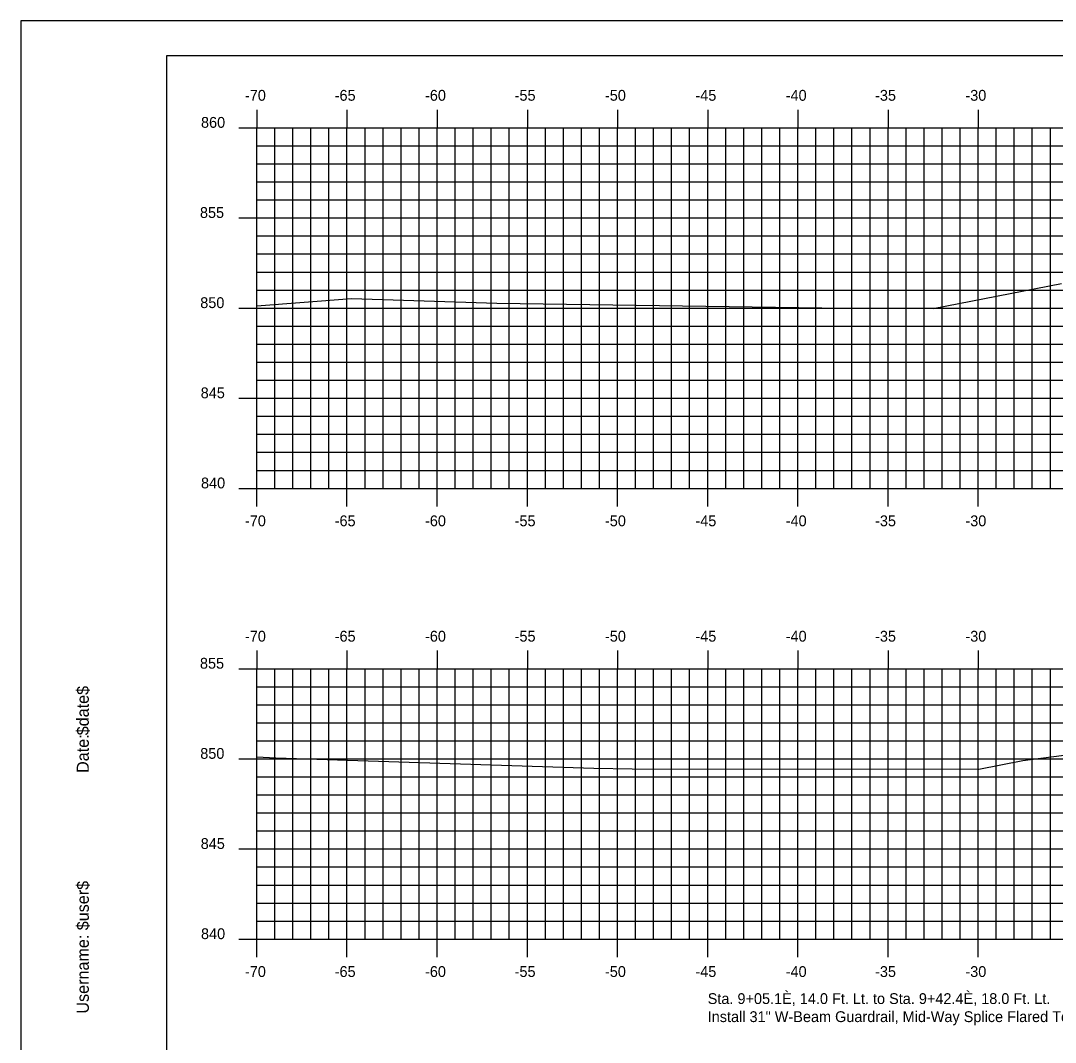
# Model space of a CAD drawing. Extents: x 2194502 to 2194968, y 863888 to 863998.
# Drawn here: x 2194615.4 to 2194672.8, y 863941.7 to 863998.4 of the extents above; entities that cross this region are included whole.
import ezdxf

# ---------------------------------------------------------------- set-up
doc = ezdxf.new("R2010")
doc.units = 0
for name, color, linetype in [('ANNOTATION', 7, 'Continuous'), ('BORDER', 7, 'Continuous'), ('H_V ANNOTATION', 7, 'Continuous'), ('MAJOR', 7, 'Continuous'), ('MINOR', 7, 'Continuous'), ('PLOT BOUNDARY', 7, 'Continuous'), ('S_Roadway_Centerline', 7, 'Continuous')]:
    doc.layers.add(name, color=color, linetype=linetype)

msp = doc.modelspace()

# ---------------------------------------------------------------- linework, layer by layer
at = {"layer": 'BORDER'}
msp.add_lwpolyline([(2194623.499, 863891.446), (2194783.499, 863891.446), (2194783.499, 863996.446), (2194623.499, 863996.446)], close=True, dxfattribs=at)
at = {"layer": 'MAJOR'}
for p, q in [((2194628.499, 863993.448), (2194628.499, 863992.446)), ((2194633.499, 863993.448), (2194633.499, 863992.446)), ((2194638.499, 863993.448), (2194638.499, 863992.446)), ((2194643.499, 863993.448), (2194643.499, 863992.446)), ((2194648.499, 863993.448), (2194648.499, 863992.446)), ((2194653.499, 863993.448), (2194653.499, 863992.446)), ((2194658.499, 863993.448), (2194658.499, 863992.446)), ((2194663.499, 863993.448), (2194663.499, 863992.446)), ((2194668.499, 863993.448), (2194668.499, 863992.446)), ((2194627.497, 863992.446), (2194628.499, 863992.446)), ((2194628.499, 863992.446), (2194768.499, 863992.446)), ((2194628.499, 863992.446), (2194768.499, 863992.446)), ((2194628.499, 863972.446), (2194628.499, 863992.446)), ((2194628.499, 863972.446), (2194628.499, 863992.446)), ((2194633.499, 863972.446), (2194633.499, 863992.446)), ((2194638.499, 863972.446), (2194638.499, 863992.446)), ((2194643.499, 863972.446), (2194643.499, 863992.446)), ((2194648.499, 863972.446), (2194648.499, 863992.446)), ((2194653.499, 863972.446), (2194653.499, 863992.446)), ((2194658.499, 863972.446), (2194658.499, 863992.446)), ((2194663.499, 863972.446), (2194663.499, 863992.446)), ((2194668.499, 863972.446), (2194668.499, 863992.446)), ((2194627.497, 863987.446), (2194628.499, 863987.446)), ((2194628.499, 863987.446), (2194768.499, 863987.446)), ((2194627.497, 863982.446), (2194628.499, 863982.446)), ((2194628.499, 863982.446), (2194768.499, 863982.446)), ((2194627.497, 863977.446), (2194628.499, 863977.446)), ((2194628.499, 863977.446), (2194768.499, 863977.446)), ((2194627.497, 863972.446), (2194628.499, 863972.446)), ((2194628.499, 863972.446), (2194768.499, 863972.446)), ((2194628.499, 863971.444), (2194628.499, 863972.446)), ((2194633.499, 863971.444), (2194633.499, 863972.446)), ((2194638.499, 863971.444), (2194638.499, 863972.446)), ((2194643.499, 863971.444), (2194643.499, 863972.446)), ((2194648.499, 863971.444), (2194648.499, 863972.446)), ((2194653.499, 863971.444), (2194653.499, 863972.446)), ((2194658.499, 863971.444), (2194658.499, 863972.446)), ((2194663.499, 863971.444), (2194663.499, 863972.446)), ((2194668.499, 863971.444), (2194668.499, 863972.446)), ((2194628.499, 863963.448), (2194628.499, 863962.446)), ((2194633.499, 863963.448), (2194633.499, 863962.446)), ((2194638.499, 863963.448), (2194638.499, 863962.446)), ((2194643.499, 863963.448), (2194643.499, 863962.446)), ((2194648.499, 863963.448), (2194648.499, 863962.446)), ((2194653.499, 863963.448), (2194653.499, 863962.446)), ((2194658.499, 863963.448), (2194658.499, 863962.446)), ((2194663.499, 863963.448), (2194663.499, 863962.446)), ((2194668.499, 863963.448), (2194668.499, 863962.446)), ((2194627.497, 863962.446), (2194628.499, 863962.446)), ((2194628.499, 863962.446), (2194768.499, 863962.446)), ((2194628.499, 863947.446), (2194628.499, 863962.446)), ((2194628.499, 863947.446), (2194628.499, 863962.446)), ((2194633.499, 863947.446), (2194633.499, 863962.446)), ((2194638.499, 863947.446), (2194638.499, 863962.446)), ((2194643.499, 863947.446), (2194643.499, 863962.446)), ((2194648.499, 863947.446), (2194648.499, 863962.446)), ((2194653.499, 863947.446), (2194653.499, 863962.446)), ((2194658.499, 863947.446), (2194658.499, 863962.446)), ((2194663.499, 863947.446), (2194663.499, 863962.446)), ((2194668.499, 863947.446), (2194668.499, 863962.446)), ((2194627.497, 863957.446), (2194628.499, 863957.446)), ((2194628.499, 863957.446), (2194768.499, 863957.446)), ((2194627.497, 863952.446), (2194628.499, 863952.446)), ((2194628.499, 863952.446), (2194768.499, 863952.446)), ((2194627.497, 863947.446), (2194628.499, 863947.446)), ((2194628.499, 863947.446), (2194768.499, 863947.446)), ((2194628.499, 863946.444), (2194628.499, 863947.446)), ((2194633.499, 863946.444), (2194633.499, 863947.446)), ((2194638.499, 863946.444), (2194638.499, 863947.446)), ((2194643.499, 863946.444), (2194643.499, 863947.446)), ((2194648.499, 863946.444), (2194648.499, 863947.446)), ((2194653.499, 863946.444), (2194653.499, 863947.446)), ((2194658.499, 863946.444), (2194658.499, 863947.446)), ((2194663.499, 863946.444), (2194663.499, 863947.446)), ((2194668.499, 863946.444), (2194668.499, 863947.446))]:
    msp.add_line(p, q, dxfattribs=at)
at = {"layer": 'MINOR'}
for p, q in [((2194629.499, 863972.446), (2194629.499, 863992.446)), ((2194630.499, 863972.446), (2194630.499, 863992.446)), ((2194631.499, 863972.446), (2194631.499, 863992.446)), ((2194632.499, 863972.446), (2194632.499, 863992.446)), ((2194634.499, 863972.446), (2194634.499, 863992.446)), ((2194635.499, 863972.446), (2194635.499, 863992.446)), ((2194636.499, 863972.446), (2194636.499, 863992.446)), ((2194637.499, 863972.446), (2194637.499, 863992.446)), ((2194639.499, 863972.446), (2194639.499, 863992.446)), ((2194640.499, 863972.446), (2194640.499, 863992.446)), ((2194641.499, 863972.446), (2194641.499, 863992.446)), ((2194642.499, 863972.446), (2194642.499, 863992.446)), ((2194644.499, 863972.446), (2194644.499, 863992.446)), ((2194645.499, 863972.446), (2194645.499, 863992.446)), ((2194646.499, 863972.446), (2194646.499, 863992.446)), ((2194647.499, 863972.446), (2194647.499, 863992.446)), ((2194649.499, 863972.446), (2194649.499, 863992.446)), ((2194650.499, 863972.446), (2194650.499, 863992.446)), ((2194651.499, 863972.446), (2194651.499, 863992.446)), ((2194652.499, 863972.446), (2194652.499, 863992.446)), ((2194654.499, 863972.446), (2194654.499, 863992.446)), ((2194655.499, 863972.446), (2194655.499, 863992.446)), ((2194656.499, 863972.446), (2194656.499, 863992.446)), ((2194657.499, 863972.446), (2194657.499, 863992.446)), ((2194659.499, 863972.446), (2194659.499, 863992.446)), ((2194660.499, 863972.446), (2194660.499, 863992.446)), ((2194661.499, 863972.446), (2194661.499, 863992.446)), ((2194662.499, 863972.446), (2194662.499, 863992.446)), ((2194664.499, 863972.446), (2194664.499, 863992.446)), ((2194665.499, 863972.446), (2194665.499, 863992.446)), ((2194666.499, 863972.446), (2194666.499, 863992.446)), ((2194667.499, 863972.446), (2194667.499, 863992.446)), ((2194669.499, 863972.446), (2194669.499, 863992.446)), ((2194670.499, 863972.446), (2194670.499, 863992.446)), ((2194671.499, 863972.446), (2194671.499, 863992.446)), ((2194672.499, 863972.446), (2194672.499, 863992.446)), ((2194628.499, 863991.446), (2194768.499, 863991.446)), ((2194628.499, 863991.446), (2194629.501, 863991.446)), ((2194628.499, 863990.446), (2194768.499, 863990.446)), ((2194628.499, 863990.446), (2194629.501, 863990.446)), ((2194628.499, 863989.446), (2194768.499, 863989.446)), ((2194628.499, 863989.446), (2194629.501, 863989.446)), ((2194628.499, 863988.446), (2194768.499, 863988.446)), ((2194628.499, 863988.446), (2194629.501, 863988.446)), ((2194628.499, 863986.446), (2194768.499, 863986.446)), ((2194628.499, 863986.446), (2194629.501, 863986.446)), ((2194628.499, 863985.446), (2194768.499, 863985.446)), ((2194628.499, 863985.446), (2194629.501, 863985.446)), ((2194628.499, 863984.446), (2194768.499, 863984.446)), ((2194628.499, 863984.446), (2194629.501, 863984.446)), ((2194628.499, 863983.446), (2194768.499, 863983.446)), ((2194628.499, 863983.446), (2194629.501, 863983.446)), ((2194628.499, 863981.446), (2194768.499, 863981.446)), ((2194628.499, 863981.446), (2194629.501, 863981.446)), ((2194628.499, 863980.446), (2194768.499, 863980.446)), ((2194628.499, 863980.446), (2194629.501, 863980.446)), ((2194628.499, 863979.446), (2194768.499, 863979.446)), ((2194628.499, 863979.446), (2194629.501, 863979.446)), ((2194628.499, 863978.446), (2194768.499, 863978.446)), ((2194628.499, 863978.446), (2194629.501, 863978.446)), ((2194628.499, 863976.446), (2194768.499, 863976.446)), ((2194628.499, 863976.446), (2194629.501, 863976.446)), ((2194628.499, 863975.446), (2194768.499, 863975.446)), ((2194628.499, 863975.446), (2194629.501, 863975.446)), ((2194628.499, 863974.446), (2194768.499, 863974.446)), ((2194628.499, 863974.446), (2194629.501, 863974.446)), ((2194628.499, 863973.446), (2194768.499, 863973.446)), ((2194628.499, 863973.446), (2194629.501, 863973.446)), ((2194629.499, 863947.446), (2194629.499, 863962.446)), ((2194630.499, 863947.446), (2194630.499, 863962.446)), ((2194631.499, 863947.446), (2194631.499, 863962.446)), ((2194632.499, 863947.446), (2194632.499, 863962.446)), ((2194634.499, 863947.446), (2194634.499, 863962.446)), ((2194635.499, 863947.446), (2194635.499, 863962.446)), ((2194636.499, 863947.446), (2194636.499, 863962.446)), ((2194637.499, 863947.446), (2194637.499, 863962.446)), ((2194639.499, 863947.446), (2194639.499, 863962.446)), ((2194640.499, 863947.446), (2194640.499, 863962.446)), ((2194641.499, 863947.446), (2194641.499, 863962.446)), ((2194642.499, 863947.446), (2194642.499, 863962.446)), ((2194644.499, 863947.446), (2194644.499, 863962.446)), ((2194645.499, 863947.446), (2194645.499, 863962.446)), ((2194646.499, 863947.446), (2194646.499, 863962.446)), ((2194647.499, 863947.446), (2194647.499, 863962.446)), ((2194649.499, 863947.446), (2194649.499, 863962.446)), ((2194650.499, 863947.446), (2194650.499, 863962.446)), ((2194651.499, 863947.446), (2194651.499, 863962.446)), ((2194652.499, 863947.446), (2194652.499, 863962.446)), ((2194654.499, 863947.446), (2194654.499, 863962.446)), ((2194655.499, 863947.446), (2194655.499, 863962.446)), ((2194656.499, 863947.446), (2194656.499, 863962.446)), ((2194657.499, 863947.446), (2194657.499, 863962.446)), ((2194659.499, 863947.446), (2194659.499, 863962.446)), ((2194660.499, 863947.446), (2194660.499, 863962.446)), ((2194661.499, 863947.446), (2194661.499, 863962.446)), ((2194662.499, 863947.446), (2194662.499, 863962.446)), ((2194664.499, 863947.446), (2194664.499, 863962.446)), ((2194665.499, 863947.446), (2194665.499, 863962.446)), ((2194666.499, 863947.446), (2194666.499, 863962.446)), ((2194667.499, 863947.446), (2194667.499, 863962.446)), ((2194669.499, 863947.446), (2194669.499, 863962.446)), ((2194670.499, 863947.446), (2194670.499, 863962.446)), ((2194671.499, 863947.446), (2194671.499, 863962.446)), ((2194672.499, 863947.446), (2194672.499, 863962.446)), ((2194628.499, 863961.446), (2194768.499, 863961.446)), ((2194628.499, 863961.446), (2194629.501, 863961.446)), ((2194628.499, 863960.446), (2194768.499, 863960.446)), ((2194628.499, 863960.446), (2194629.501, 863960.446)), ((2194628.499, 863959.446), (2194768.499, 863959.446)), ((2194628.499, 863959.446), (2194629.501, 863959.446)), ((2194628.499, 863958.446), (2194768.499, 863958.446)), ((2194628.499, 863958.446), (2194629.501, 863958.446)), ((2194628.499, 863956.446), (2194768.499, 863956.446)), ((2194628.499, 863956.446), (2194629.501, 863956.446)), ((2194628.499, 863955.446), (2194768.499, 863955.446)), ((2194628.499, 863955.446), (2194629.501, 863955.446)), ((2194628.499, 863954.446), (2194768.499, 863954.446)), ((2194628.499, 863954.446), (2194629.501, 863954.446)), ((2194628.499, 863953.446), (2194768.499, 863953.446)), ((2194628.499, 863953.446), (2194629.501, 863953.446)), ((2194628.499, 863951.446), (2194768.499, 863951.446)), ((2194628.499, 863951.446), (2194629.501, 863951.446)), ((2194628.499, 863950.446), (2194768.499, 863950.446)), ((2194628.499, 863950.446), (2194629.501, 863950.446)), ((2194628.499, 863949.446), (2194768.499, 863949.446)), ((2194628.499, 863949.446), (2194629.501, 863949.446)), ((2194628.499, 863948.446), (2194768.499, 863948.446)), ((2194628.499, 863948.446), (2194629.501, 863948.446))]:
    msp.add_line(p, q, dxfattribs=at)
at = {"layer": 'PLOT BOUNDARY'}
msp.add_lwpolyline([(2194615.406, 863888.387), (2194785.406, 863888.387), (2194785.406, 863998.387), (2194615.406, 863998.387)], close=True, dxfattribs=at)
at = {"layer": 'S_Roadway_Centerline'}
for points in [[(2194628.499, 863982.562), (2194633.753, 863982.979), (2194641.809, 863982.714), (2194661.127, 863982.435), (2194666, 863982.427), (2194673.123, 863983.818)], [(2194628.499, 863957.55), (2194629.552, 863957.508), (2194647.188, 863956.927), (2194649.317, 863956.897), (2194668.53, 863956.866), (2194670.976, 863957.344), (2194680.42, 863958.572)]]:
    msp.add_lwpolyline(points, dxfattribs=at)

# ---------------------------------------------------------------- texts
at = {"layer": 'ANNOTATION'}
for s, p in [('Sta. 9+05.1È, 14.0 Ft. Lt. to Sta. 9+42.4È, 18.0 Ft. Lt.', (2194653.499, 863943.846)), ('Install 31" W-Beam Guardrail, Mid-Way Splice Flared Terminal', (2194653.499, 863942.844))]:
    msp.add_text(s, height=0.6, dxfattribs=at).set_placement(p)
at = {"layer": 'BORDER'}
for s, p in [('$date$', (2194619.184, 863958.751)), ('Date:', (2194619.184, 863956.663)), ('$user$', (2194619.184, 863947.937)), ('Username:', (2194619.184, 863943.314))]:
    msp.add_text(s, height=0.6696, rotation=90, dxfattribs=at).set_placement(p)
at = {"layer": 'H_V ANNOTATION'}
for s, p in [('-70', (2194627.841, 863993.946)), ('-65', (2194632.817, 863993.946)), ('-60', (2194637.825, 863993.946)), ('-55', (2194642.795, 863993.946)), ('-50', (2194647.803, 863993.946)), ('-45', (2194652.817, 863993.946)), ('-40', (2194657.825, 863993.946)), ('-35', (2194662.779, 863993.946)), ('-30', (2194667.787, 863993.946)), ('860', (2194625.404, 863992.446)), ('855', (2194625.345, 863987.446)), ('850', (2194625.361, 863982.446)), ('845', (2194625.388, 863977.446)), ('840', (2194625.404, 863972.446)), ('-70', (2194627.841, 863970.346)), ('-65', (2194632.817, 863970.346)), ('-60', (2194637.825, 863970.346)), ('-55', (2194642.795, 863970.346)), ('-50', (2194647.803, 863970.346)), ('-45', (2194652.817, 863970.346)), ('-40', (2194657.825, 863970.346)), ('-35', (2194662.779, 863970.346)), ('-30', (2194667.787, 863970.346)), ('-70', (2194627.841, 863963.946)), ('-65', (2194632.817, 863963.946)), ('-60', (2194637.825, 863963.946)), ('-55', (2194642.795, 863963.946)), ('-50', (2194647.803, 863963.946)), ('-45', (2194652.817, 863963.946)), ('-40', (2194657.825, 863963.946)), ('-35', (2194662.779, 863963.946)), ('-30', (2194667.787, 863963.946)), ('855', (2194625.345, 863962.446)), ('850', (2194625.361, 863957.446)), ('845', (2194625.388, 863952.446)), ('840', (2194625.404, 863947.446)), ('-70', (2194627.841, 863945.346)), ('-65', (2194632.817, 863945.346)), ('-60', (2194637.825, 863945.346)), ('-55', (2194642.795, 863945.346)), ('-50', (2194647.803, 863945.346)), ('-45', (2194652.817, 863945.346)), ('-40', (2194657.825, 863945.346)), ('-35', (2194662.779, 863945.346)), ('-30', (2194667.787, 863945.346))]:
    msp.add_text(s, height=0.6, dxfattribs=at).set_placement(p)

doc.saveas('drawing.dxf')
